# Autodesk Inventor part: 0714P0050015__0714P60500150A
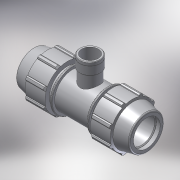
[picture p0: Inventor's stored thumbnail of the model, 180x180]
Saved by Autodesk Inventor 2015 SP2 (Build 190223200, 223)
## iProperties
Created: 2017-02
Part Number: 0714P0050015__0714P60500150A
Material: PVC-Piping
Description: PLASSON TEE FEMALE ADAPTOR WITHOUT STOP 50-1.1/2"
Document SubType Name: Modeling
Designer: KIM
Mass: 92.6774 g
Surface Area: 199.44 cm^2
Volume: 66.1981 cm^3
Density: 1.4 g/cm^3
Appearance: Smooth - White
Author: KIM
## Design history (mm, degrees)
derived "0714P0.ipt"
feature "Solid1::0714P0.ipt"
feature "Solid2::0714P0.ipt"
tag "TaggingFeature1"
body "Solid1"
other parameters: "d4" = 10.16667, "d5" = 29.28, "d7" = 96, "d11" = 4.06667, "d13" = 120 deg, "d15" = 12 deg, "d16" = 83.52, "d18" = 2.5, "d19" = 35 deg, "d20" = 17.5 deg, "d21" = 89.28, "d23" = 0, "d25" = 360 deg, "d27" = 1.92, "d33" = 1, "d42" = 43.92, "d43" = 2.88, "d46" = 1.5, "d68" = 7.32, "d72" = 76, "d76" = 44.845, "d80" = 1.34535, "d91" = 72, "d93" = 93, "d95" = 45, "d112" = 25, "d115" = 56.05625, "d116" = 135 deg, "d117" = 51.57175, "d118" = 244, "d119" = 45, "d121" = 0, "d122" = 40.5, "d124" = 0, "d128" = 0, "d129" = 5, "d130" = 7.5, "d131" = 0.3, "d132" = 0.3, "d133" = 56.05625, "E_" = 96, "A_" = 76, "l_" = 93, "l_2" = 25, "Rp_" = 44.845, "H_" = 244
